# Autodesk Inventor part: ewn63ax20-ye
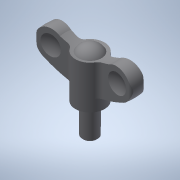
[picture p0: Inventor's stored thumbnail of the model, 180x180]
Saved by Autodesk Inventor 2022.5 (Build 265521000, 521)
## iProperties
Created: 2017-05
Part Number: ewn63ax20-ye
Material: 一般
Document SubType Name: Modeling
Designer: imaocorp
Density: 1 g/cm^3
Appearance: 既定
Author: imaocorp
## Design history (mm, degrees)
node "ewn63ax20-ye.x_t1"
node "ewn63ax20-ye"
node "Base1"
